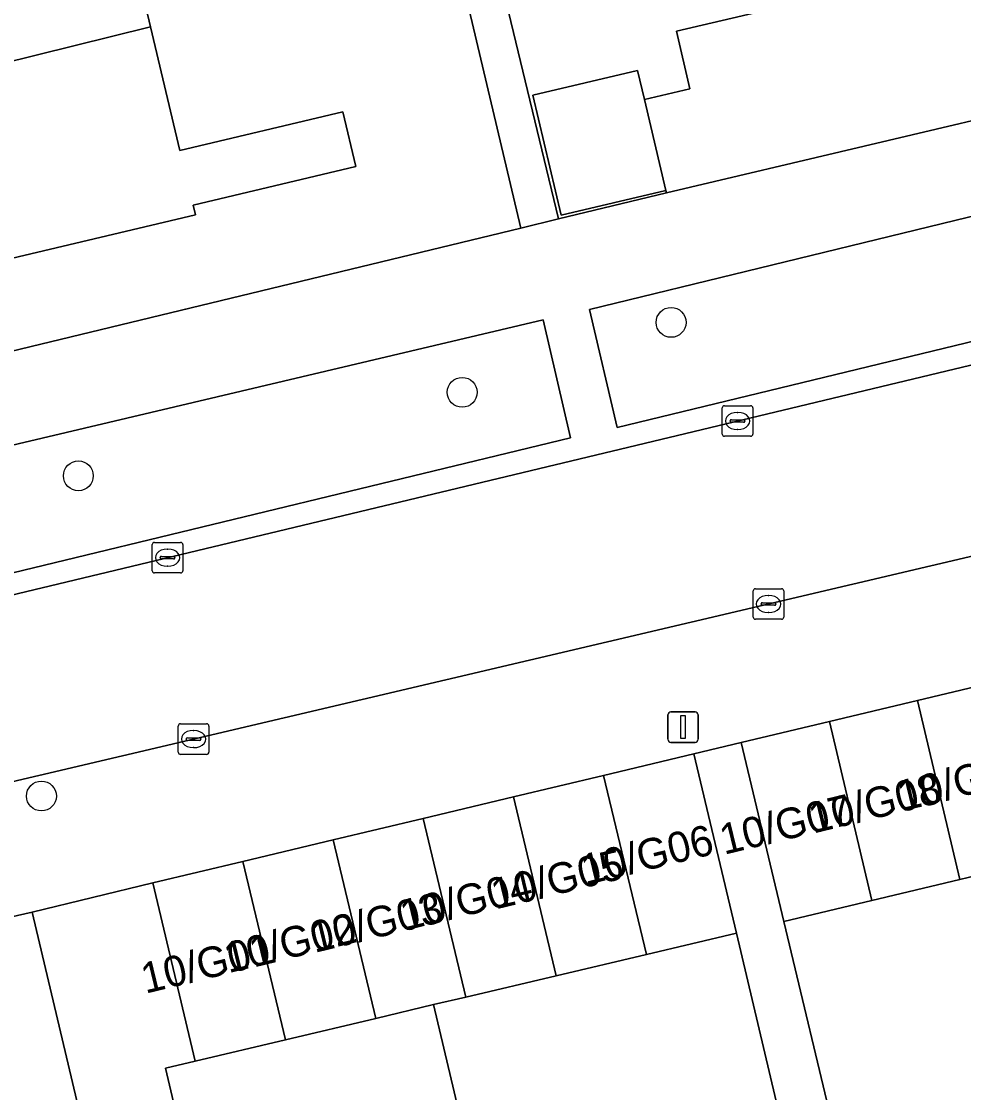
# Model space of a CAD drawing. Extents: x 158031 to 159244, y 380104 to 381214.
# Drawn here: x 158559.44 to 158590.29, y 380761.24 to 380796.3 of the extents above; entities that cross this region are included whole.
import ezdxf

# ---------------------------------------------------------------- set-up
doc = ezdxf.new("R2010")
doc.units = 0
for name, color, linetype in [('IMGEO_Boom', 7, 'Continuous'), ('IMGEO_Erf', 7, 'Continuous'), ('IMGEO_Groenvoorziening', 7, 'Continuous'), ('IMGEO_Kolk', 7, 'Continuous'), ('IMGEO_Lichtmast', 7, 'Continuous'), ('IMGEO_Pand', 7, 'Continuous'), ('IMGEO_Pand_nummerreeks', 7, 'Continuous'), ('IMGEO_Rijbaan_lokaal_open', 7, 'Continuous'), ('IMGEO_Voetpad_open', 7, 'Continuous')]:
    doc.layers.add(name, color=color, linetype=linetype)

msp = doc.modelspace()

# ---------------------------------------------------------------- linework, layer by layer
at = {"layer": 'IMGEO_Boom'}
for centre in [(158580.71, 380786.449), (158573.873, 380784.16), (158561.307, 380781.427), (158560.097, 380770.946)]:
    msp.add_circle(centre, 0.489, dxfattribs=at)
at = {"layer": 'IMGEO_Erf'}
for points in [[(158568.7, 380824.316), (158577.028, 380789.836), (158580.558, 380790.689), (158580.541, 380790.762), (158577.115, 380789.953), (158576.186, 380793.887), (158579.612, 380794.695), (158579.837, 380793.743), (158581.329, 380794.095), (158580.884, 380795.981), (158586.213, 380797.239)], [(158544.566, 380816.468), (158551.938, 380785.363), (158552.008, 380785.214), (158552.091, 380785.071), (158552.186, 380784.936), (158552.293, 380784.811), (158552.411, 380784.695), (158552.539, 380784.591), (158552.675, 380784.498), (158552.82, 380784.418), (158552.971, 380784.351), (158553.127, 380784.298), (158553.287, 380784.259), (158553.45, 380784.234), (158553.615, 380784.224), (158553.78, 380784.229), (158553.836, 380784.234), (158575.794, 380789.538), (158568.094, 380822.042)], [(158562.747, 380800.007), (158563.667, 380796.124), (158564.626, 380792.079), (158569.966, 380793.345), (158570.391, 380791.548), (158565.064, 380790.285), (158565.138, 380789.974), (158556.423, 380787.909), (158554.986, 380793.976), (158553.597, 380799.838)], [(158588.426, 380742.845), (158582.853, 380766.459), (158579.901, 380765.762), (158576.947, 380765.064), (158573.993, 380764.367), (158572.935, 380764.117), (158573.95, 380759.83)]]:
    msp.add_lwpolyline(points, dxfattribs=at)
for points in [[(158598.899, 380750), (158598.561, 380751.427), (158597.627, 380755.367), (158592.275, 380754.116), (158591.833, 380756.006), (158591.411, 380757.814), (158596.728, 380759.056), (158595.788, 380763.076), (158594.324, 380762.734), (158593.901, 380764.544), (158592.892, 380768.863), (158590.165, 380768.213), (158587.286, 380767.526), (158584.406, 380766.84), (158586.112, 380759.687), (158591.465, 380737.246), (158601.276, 380739.54), (158600.309, 380743.68), (158595.041, 380742.448), (158594.593, 380744.364), (158594.166, 380746.188), (158599.506, 380747.436)], [(158568.345, 380744.309), (158567.002, 380750), (158566.957, 380750.189), (158565.582, 380756.016), (158564.16, 380762.039), (158565.133, 380762.27), (158563.743, 380768.102), (158559.795, 380767.141), (158563.854, 380750), (158568.185, 380731.708), (158571.154, 380732.409), (158569.726, 380738.457)]]:
    msp.add_lwpolyline(points, close=True, dxfattribs=at)
at = {"layer": 'IMGEO_Groenvoorziening'}
for points in [[(158601.053, 380788.365), (158600.252, 380792.284), (158578.035, 380786.868), (158578.947, 380783.008)], [(158577.413, 380782.673), (158576.522, 380786.533), (158552.994, 380780.981), (158553.963, 380777.002)]]:
    msp.add_lwpolyline(points, close=True, dxfattribs=at)
at = {"layer": 'IMGEO_Kolk'}
for p, q in [((158582.461, 380783.721), (158583.313, 380783.721)), ((158582.386, 380782.795), (158582.386, 380783.647)), ((158582.874, 380783.501), (158582.899, 380783.501)), ((158583.387, 380783.647), (158583.387, 380782.795)), ((158582.645, 380783.215), (158582.645, 380783.227)), ((158583.083, 380783.178), (158582.685, 380783.178)), ((158582.688, 380783.264), (158583.086, 380783.264)), ((158583.129, 380783.227), (158583.129, 380783.215)), ((158583.313, 380782.721), (158582.461, 380782.721)), ((158582.897, 380782.941), (158582.872, 380782.941)), ((158563.727, 380778.322), (158563.727, 380779.174)), ((158563.802, 380779.248), (158564.654, 380779.248)), ((158564.728, 380779.174), (158564.728, 380778.322)), ((158563.986, 380778.742), (158563.986, 380778.754)), ((158564.029, 380778.791), (158564.427, 380778.791)), ((158564.215, 380779.028), (158564.24, 380779.028)), ((158564.47, 380778.754), (158564.47, 380778.742)), ((158564.424, 380778.705), (158564.026, 380778.705)), ((158564.238, 380778.468), (158564.213, 380778.468)), ((158564.654, 380778.248), (158563.802, 380778.248)), ((158583.473, 380777.731), (158584.325, 380777.731)), ((158583.398, 380776.805), (158583.398, 380777.657)), ((158583.886, 380777.511), (158583.911, 380777.511)), ((158584.399, 380777.657), (158584.399, 380776.805)), ((158583.657, 380777.225), (158583.657, 380777.237)), ((158584.095, 380777.188), (158583.697, 380777.188)), ((158583.7, 380777.274), (158584.098, 380777.274)), ((158584.141, 380777.237), (158584.141, 380777.225)), ((158584.325, 380776.731), (158583.473, 380776.731)), ((158583.909, 380776.951), (158583.884, 380776.951)), ((158564.578, 380772.384), (158564.578, 380773.236)), ((158564.653, 380773.31), (158565.505, 380773.31)), ((158565.579, 380773.236), (158565.579, 380772.384)), ((158564.837, 380772.804), (158564.837, 380772.816)), ((158564.88, 380772.853), (158565.278, 380772.853)), ((158565.066, 380773.09), (158565.091, 380773.09)), ((158565.321, 380772.816), (158565.321, 380772.804)), ((158565.275, 380772.767), (158564.877, 380772.767)), ((158565.089, 380772.53), (158565.064, 380772.53)), ((158565.505, 380772.31), (158564.653, 380772.31))]:
    msp.add_line(p, q, dxfattribs=at)
for points in [[(158582.461, 380783.721), (158583.313, 380783.721)], [(158582.386, 380782.795), (158582.386, 380783.647)], [(158583.387, 380783.647), (158583.387, 380782.795)], [(158583.313, 380782.721), (158582.461, 380782.721)], [(158563.727, 380778.322), (158563.727, 380779.174)], [(158563.802, 380779.248), (158564.654, 380779.248)], [(158564.728, 380779.174), (158564.728, 380778.322)], [(158564.654, 380778.248), (158563.802, 380778.248)], [(158583.473, 380777.731), (158584.325, 380777.731)], [(158583.398, 380776.805), (158583.398, 380777.657)], [(158584.399, 380777.657), (158584.399, 380776.805)], [(158584.325, 380776.731), (158583.473, 380776.731)], [(158564.578, 380772.384), (158564.578, 380773.236)], [(158564.653, 380773.31), (158565.505, 380773.31)], [(158565.579, 380773.236), (158565.579, 380772.384)], [(158565.505, 380772.31), (158564.653, 380772.31)]]:
    msp.add_lwpolyline(points, dxfattribs=at)
for centre, radius, start, end in [((158582.463, 380783.645), 0.0765, 91.552, 178.448), ((158582.463, 380783.645), 0.0765, 91.552, 178.448), ((158583.311, 380783.645), 0.0765, 1.552, 88.448), ((158583.311, 380783.645), 0.0765, 1.552, 88.448), ((158582.685, 380783.224), 0.0403, 85.8775, 175.7526), ((158582.682, 380783.214), 0.0366, 178.938, 274.7102), ((158583.086, 380783.221), 0.043, 264.8664, 352.4533), ((158583.09, 380783.226), 0.0386, 1.7309, 96.639), ((158582.463, 380782.797), 0.0765, 181.552, 268.448), ((158582.463, 380782.797), 0.0765, 181.552, 268.448), ((158583.311, 380782.797), 0.0765, 271.552, 358.448), ((158583.311, 380782.797), 0.0765, 271.552, 358.448), ((158563.804, 380779.172), 0.0765, 91.552, 178.448), ((158563.804, 380779.172), 0.0765, 91.552, 178.448), ((158564.652, 380779.172), 0.0765, 1.552, 88.448), ((158564.652, 380779.172), 0.0765, 1.552, 88.448), ((158564.026, 380778.751), 0.0403, 85.8775, 175.7526), ((158564.023, 380778.741), 0.0366, 178.938, 274.7102), ((158564.427, 380778.748), 0.043, 264.8664, 352.4533), ((158564.431, 380778.753), 0.0386, 1.7309, 96.639), ((158563.804, 380778.324), 0.0765, 181.552, 268.448), ((158563.804, 380778.324), 0.0765, 181.552, 268.448), ((158564.652, 380778.324), 0.0765, 271.552, 358.448), ((158564.652, 380778.324), 0.0765, 271.552, 358.448), ((158583.475, 380777.655), 0.0765, 91.552, 178.448), ((158583.475, 380777.655), 0.0765, 91.552, 178.448), ((158584.323, 380777.655), 0.0765, 1.552, 88.448), ((158584.323, 380777.655), 0.0765, 1.552, 88.448), ((158583.697, 380777.234), 0.0403, 85.8775, 175.7526), ((158583.694, 380777.224), 0.0366, 178.938, 274.7102), ((158584.098, 380777.231), 0.043, 264.8664, 352.4533), ((158584.102, 380777.236), 0.0386, 1.7309, 96.639), ((158583.475, 380776.807), 0.0765, 181.552, 268.448), ((158583.475, 380776.807), 0.0765, 181.552, 268.448), ((158584.323, 380776.807), 0.0765, 271.552, 358.448), ((158584.323, 380776.807), 0.0765, 271.552, 358.448), ((158564.655, 380773.234), 0.0765, 91.552, 178.448), ((158564.655, 380773.234), 0.0765, 91.552, 178.448), ((158565.503, 380773.234), 0.0765, 1.552, 88.448), ((158565.503, 380773.234), 0.0765, 1.552, 88.448), ((158564.877, 380772.813), 0.0403, 85.8775, 175.7526), ((158564.874, 380772.803), 0.0366, 178.938, 274.7102), ((158565.278, 380772.81), 0.043, 264.8664, 352.4533), ((158565.282, 380772.815), 0.0386, 1.7309, 96.639), ((158564.655, 380772.386), 0.0765, 181.552, 268.448), ((158564.655, 380772.386), 0.0765, 181.552, 268.448), ((158565.503, 380772.386), 0.0765, 271.552, 358.448), ((158565.503, 380772.386), 0.0765, 271.552, 358.448)]:
    msp.add_arc(centre, radius, start, end, dxfattribs=at)
for centre, major_axis, ratio, start_param, end_param in [((158582.873, 380783.221), (-0.387, 0.002), 0.722429, 4.712389, 7.853982), ((158582.898, 380783.221), (-0.39, 0.002), 0.717154, 1.570796, 4.712389), ((158564.214, 380778.748), (-0.387, 0.002), 0.722429, 4.712389, 7.853982), ((158564.239, 380778.748), (-0.39, 0.002), 0.717154, 1.570796, 4.712389), ((158583.885, 380777.231), (-0.387, 0.002), 0.722429, 4.712389, 7.853982), ((158583.91, 380777.231), (-0.39, 0.002), 0.717154, 1.570796, 4.712389), ((158565.065, 380772.81), (-0.387, 0.002), 0.722429, 4.712389, 7.853982), ((158565.09, 380772.81), (-0.39, 0.002), 0.717154, 1.570796, 4.712389)]:
    msp.add_ellipse(centre, major_axis=major_axis, ratio=ratio, start_param=start_param, end_param=end_param, dxfattribs=at)
at = {"layer": 'IMGEO_Lichtmast'}
for p, q in [((158580.604, 380772.802), (158580.604, 380773.602)), ((158580.604, 380773.602), (158580.604, 380772.802)), ((158580.704, 380773.702), (158581.494, 380773.702)), ((158581.494, 380773.702), (158580.704, 380773.702)), ((158581.594, 380773.602), (158581.594, 380772.802)), ((158581.594, 380772.802), (158581.594, 380773.602)), ((158581.494, 380772.702), (158580.704, 380772.702)), ((158580.704, 380772.702), (158581.494, 380772.702))]:
    msp.add_line(p, q, dxfattribs=at)
msp.add_lwpolyline([(158581.024, 380773.577), (158581.174, 380773.577), (158581.174, 380772.827), (158581.024, 380772.827), (158581.024, 380773.577)], dxfattribs=at)
for centre, start, end in [((158580.704, 380773.602), 90, 180), ((158580.704, 380773.602), 90, 180), ((158581.494, 380773.602), 0, 90), ((158581.494, 380773.602), 360, 90), ((158580.704, 380772.802), 180, 270), ((158580.704, 380772.802), 180, 270), ((158581.494, 380772.802), 270, 0), ((158581.494, 380772.802), 270, 0)]:
    msp.add_arc(centre, 0.1, start, end, dxfattribs=at)
at = {"layer": 'IMGEO_Pand'}
for points in [[(158563.667, 380796.124), (158562.747, 380800.007), (158568.193, 380801.298), (158567.735, 380803.227), (158553.597, 380799.838), (158554.986, 380793.976)], [(158595.447, 380797.204), (158594.024, 380803.234), (158585.276, 380801.21), (158586.213, 380797.239), (158580.884, 380795.981), (158581.329, 380794.095), (158579.837, 380793.743), (158580.541, 380790.762), (158580.558, 380790.689), (158593.5, 380793.746), (158592.829, 380796.586)], [(158563.667, 380796.124), (158554.986, 380793.976), (158556.423, 380787.909), (158565.138, 380789.974), (158565.064, 380790.285), (158570.391, 380791.548), (158569.966, 380793.345), (158564.626, 380792.079)], [(158579.837, 380793.743), (158579.612, 380794.695), (158576.186, 380793.887), (158577.115, 380789.953), (158580.541, 380790.762)], [(158591.657, 380774.759), (158588.778, 380774.072), (158590.165, 380768.213), (158592.892, 380768.863), (158593.045, 380768.899)], [(158587.286, 380767.526), (158590.165, 380768.213), (158588.778, 380774.072), (158585.898, 380773.386)], [(158587.286, 380767.526), (158585.898, 380773.386), (158583.009, 380772.697), (158584.406, 380766.84)], [(158578.503, 380771.622), (158579.901, 380765.762), (158582.853, 380766.459), (158581.455, 380772.326)], [(158578.503, 380771.622), (158575.551, 380770.918), (158576.947, 380765.064), (158579.901, 380765.762)], [(158573.993, 380764.367), (158576.947, 380765.064), (158575.551, 380770.918), (158572.599, 380770.214)], [(158571.04, 380763.668), (158572.935, 380764.117), (158573.993, 380764.367), (158572.599, 380770.214), (158569.647, 380769.51)], [(158566.695, 380768.806), (158568.087, 380762.969), (158571.04, 380763.668), (158569.647, 380769.51)], [(158566.695, 380768.806), (158563.743, 380768.102), (158565.133, 380762.27), (158568.087, 380762.969)], [(158572.935, 380764.117), (158571.04, 380763.668), (158568.087, 380762.969), (158565.133, 380762.27), (158564.16, 380762.039), (158565.582, 380756.016), (158574.328, 380758.042), (158575.845, 380758.393), (158575.422, 380760.179), (158573.95, 380759.83)]]:
    msp.add_lwpolyline(points, close=True, dxfattribs=at)
at = {"layer": 'IMGEO_Rijbaan_lokaal_open'}
msp.add_lwpolyline([(158602.537, 380781.61), (158601.167, 380787.602), (158550.781, 380775.523), (158542.939, 380773.643), (158544.131, 380767.891)], close=True, dxfattribs=at)
at = {"layer": 'IMGEO_Voetpad_open'}
for points in [[(158575.794, 380789.538), (158577.028, 380789.836), (158568.7, 380824.316), (158567.641, 380824.075), (158561.065, 380852.917), (158559.623, 380859.031), (158562.638, 380859.742), (158562.085, 380862.085), (158554.603, 380860.32), (158555.166, 380857.934), (158558.183, 380858.646), (158559.622, 380852.545), (158566.537, 380823.228), (158556.446, 380820.79), (158552.507, 380819.856), (158547.641, 380818.703), (158544.228, 380817.894), (158544.566, 380816.468), (158549.386, 380817.61), (158554.252, 380818.763), (158558.068, 380819.667), (158568.094, 380822.042)], [(158578.035, 380786.868), (158600.252, 380792.284), (158599.515, 380795.166), (158593.5, 380793.746), (158580.558, 380790.689), (158577.028, 380789.836), (158575.794, 380789.538), (158553.836, 380784.234), (158548.998, 380783.065), (158550.781, 380775.523), (158601.167, 380787.602), (158601.053, 380788.365), (158578.947, 380783.008)], [(158576.522, 380786.533), (158577.413, 380782.673), (158553.963, 380777.002), (158552.994, 380780.981)], [(158602.537, 380781.61), (158544.131, 380767.891), (158545.124, 380763.759), (158550.898, 380765.127), (158559.795, 380767.141), (158563.743, 380768.102), (158566.695, 380768.806), (158569.647, 380769.51), (158572.599, 380770.214), (158575.551, 380770.918), (158578.503, 380771.622), (158581.455, 380772.326), (158583.009, 380772.697), (158585.898, 380773.386), (158588.778, 380774.072), (158591.657, 380774.759), (158594.537, 380775.445), (158597.408, 380776.13), (158604.491, 380777.798)], [(158600.705, 380737.896), (158606.84, 380739.335), (158612.318, 380740.656), (158611.977, 380742.07), (158609.955, 380741.569), (158605.087, 380740.431), (158601.276, 380739.54), (158591.465, 380737.246), (158586.112, 380759.687), (158584.406, 380766.84), (158583.009, 380772.697), (158581.455, 380772.326), (158582.853, 380766.459), (158588.426, 380742.845), (158588.845, 380741.072), (158589.846, 380736.837), (158579.907, 380734.482), (158576.02, 380733.561), (158571.154, 380732.409), (158568.185, 380731.708), (158568.508, 380730.343)], [(158559.795, 380767.141), (158550.898, 380765.127), (158553.139, 380755.776), (158554.051, 380751.969), (158555.616, 380752.341), (158559.465, 380753.253), (158560.236, 380750), (158564.379, 380732.511), (158564.728, 380731.038), (158570.352, 380707.295), (158573.761, 380708.16), (158568.508, 380730.343), (158568.185, 380731.708), (158563.854, 380750)]]:
    msp.add_lwpolyline(points, close=True, dxfattribs=at)

# ---------------------------------------------------------------- texts
at = {"layer": 'IMGEO_Pand_nummerreeks'}
for s, rotation, p in [('10/G09', 13.6192, (158588.263, 380770.441)), ('10/G08', 13.6168, (158585.357, 380769.714)), ('10/G07', 13.6168, (158582.442, 380769.019)), ('10/G06', 13.6168, (158577.908, 380768.026)), ('10/G05', 13.6168, (158574.963, 380767.231)), ('10/G04', 13.6168, (158571.984, 380766.536)), ('10/G03', 13.6168, (158569.039, 380765.808)), ('10/G02', 13.6168, (158566.219, 380765.145)), ('10/G01', 13.6168, (158563.5, 380764.472))]:
    msp.add_text(s, height=1, rotation=rotation, dxfattribs=at).set_placement(p)

doc.saveas('drawing.dxf')
